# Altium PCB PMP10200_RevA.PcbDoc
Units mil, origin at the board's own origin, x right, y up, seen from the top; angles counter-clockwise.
Board outline 5387.5 x 1750 mil, 2 copper layers (Top Layer, Bottom Layer), stack 62 mil thick; 58 components, 32 nets, 132 pads, 50 vias.
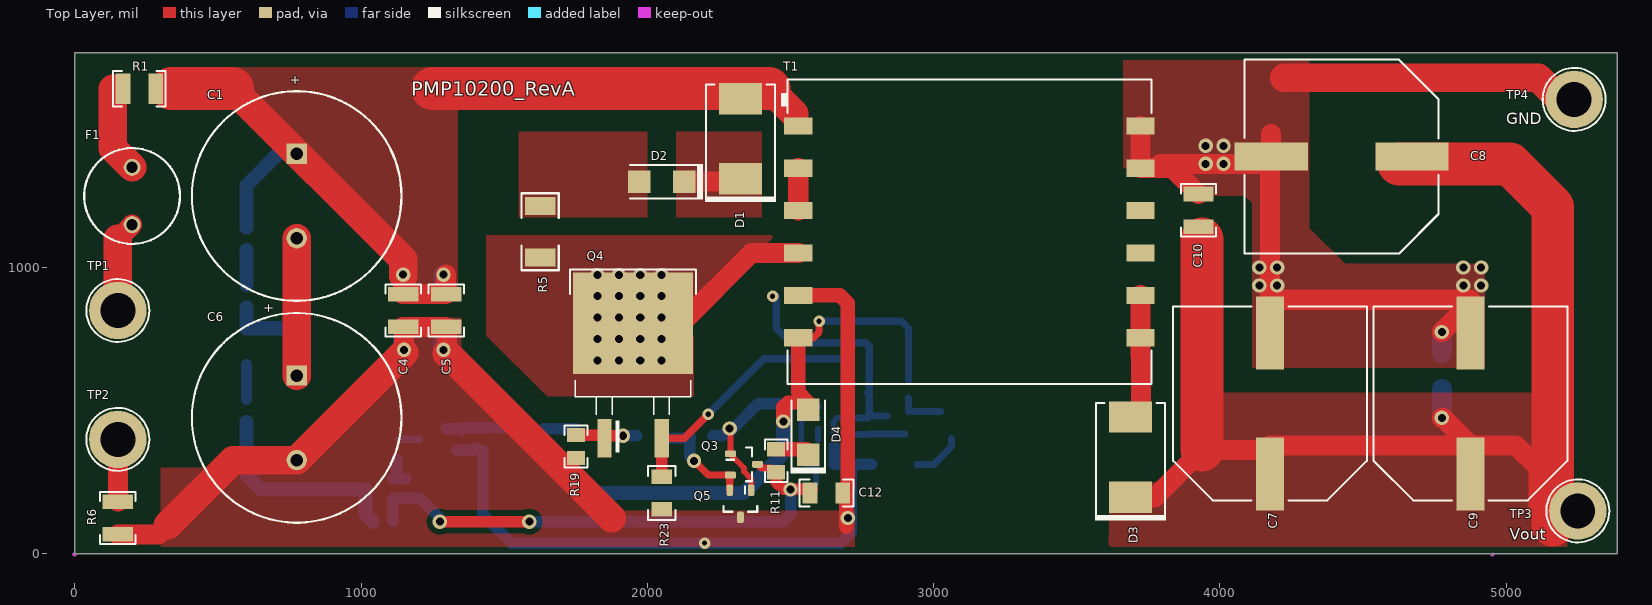
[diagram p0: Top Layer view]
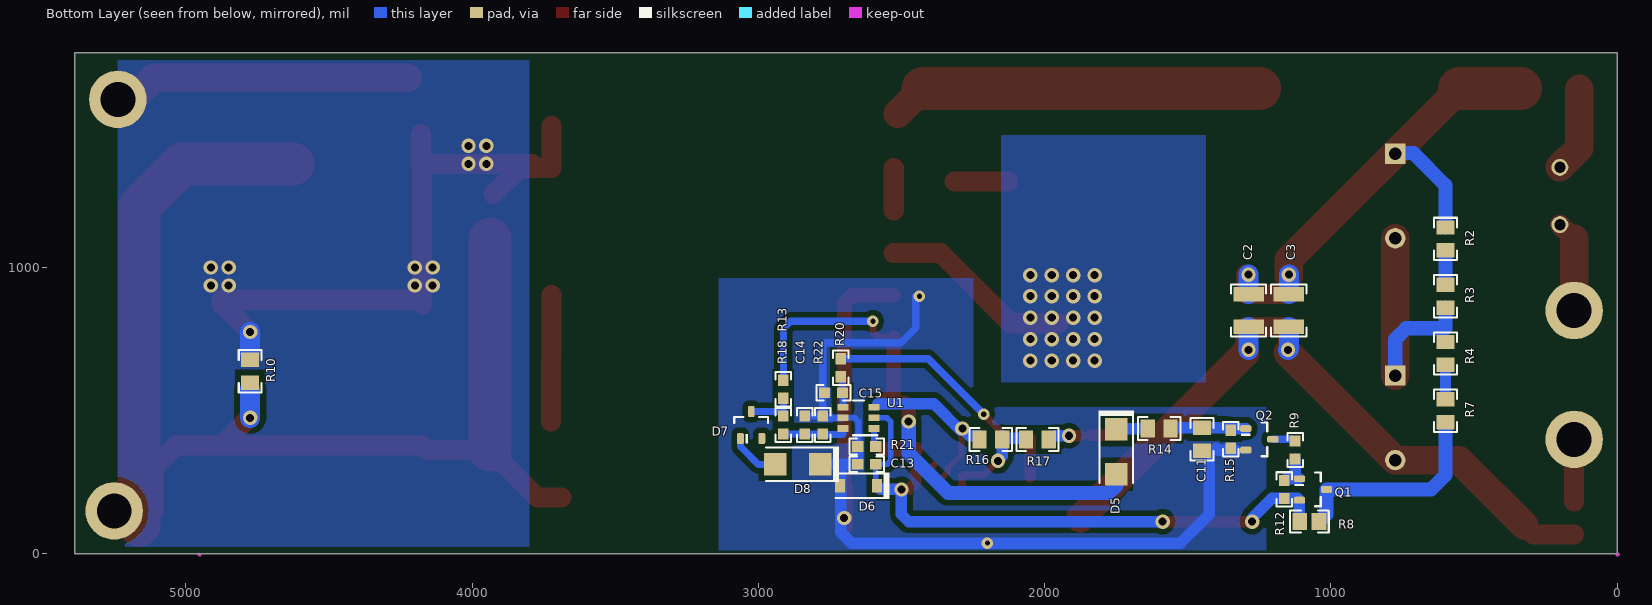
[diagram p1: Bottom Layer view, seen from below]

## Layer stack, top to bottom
Top Solder: solder mask 0.4, Solder Resist, Dk 3.5
Top Layer: signal copper 1.4
Dielectric1: core 59.2, FR-4, Dk 4.8
Bottom Layer: signal copper 1.4
Bottom Solder: solder mask 0.4, Solder Resist, Dk 3.5

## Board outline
0,0 5387.5,0 5387.5,1750 0,1750

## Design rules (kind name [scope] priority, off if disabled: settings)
AcuteAngle [All] p1: minimum=4.50000000000000E+0001 checktracksonly=FALSE
AssemblyTestPointUsage [All] p1: valid=2
Clearance Clearance_Keepouts [((IsTrack Or IsArc) And Not InPoly) And IsFree and IsKeepOut vs ((IsTrack Or IsArc) And Not InPoly) And IsFree and IsKeepOut] p1: gap=0
Clearance Clearance_BoardEdge_MountingHoles [OnCopper and InComponentClass('Mounting Holes') vs IsKeepOut] p2: gap=20
Clearance Clearance_BoardEdge_Poly [OnCopper and InPoly vs IsKeepOut] p3: gap=20
Clearance Clearance_BoardEdge [OnCopper and Not InComponentClass('Logo') and not InComponentClass('FiducialMark') and not InRegion(1000,500,4000,800) and Not IsKeepout vs IsKeepOut] p4: gap=20
Clearance Clearance_Poly [InPolygon] p5: gap=20
Clearance [All] p6: gap=7.87
ComponentClearance ComponentClearance_MountingHoles_FiducialMarks [InComponentClass('Mounting Holes') vs InComponentClass('FiducialMark')] p1: gap=50 collisioncheckmode=3 verticalgap=10 showdistances=FALSE
ComponentClearance ComponentClearance_Shunt [InComponentClass('Header') vs InComponentClass('Shunt')] p2: gap=0 collisioncheckmode=3 verticalgap=0 showdistances=FALSE
ComponentClearance ComponentClearance_Logo [InComponentClass('Logo')] p3: gap=50 collisioncheckmode=3 verticalgap=10 showdistances=FALSE
ComponentClearance ComponentClearance_ScrewToNut [(HasFootprint('NY PMS 440 0025 PH')) vs (HasFootprint('Keystone_1902C'))] p4: gap=5 collisioncheckmode=3 verticalgap=10 showdistances=FALSE
ComponentClearance ComponentClearance_MountingHoles [InComponentClass('Mounting Holes')] p5: gap=20 collisioncheckmode=3 verticalgap=100000 showdistances=FALSE
ComponentClearance ComponentClearance_SmallPassives [HasFootprint('0201*') or HasFootprint('0402*') or HasFootprint('0508') or HasFootprint('0603*') or HasFootprint('0612') or HasFootprint('0805*') or HasFootprint('0815*') or HasFootprint('0830*') or HasFootprint('1206*') or HasFootprint('1210*') or HasFootprint('1808*') or HasFootprint('1812*') or HasFootprint('1825*') or HasFootprint('2010*') or HasFootprint('2220*') or HasFootprint('2225*') or HasFootprint('2512*') or HasFootprint('2728*') or HasFootprint('3518*') vs HasFootprint('0201*') or HasFootprint('0402*') or HasFootprint('0508') or HasFootprint('0603*') or HasFootprint('0612') or HasFootprint('0805*') or HasFootprint('0815*') or HasFootprint('0830*') or HasFootprint('1206*') or HasFootprint('1210*') or HasFootprint('1808*') or HasFootprint('1812*') or HasFootprint('1825*') or HasFootprint('2010*') or HasFootprint('2220*') or HasFootprint('2225*') or HasFootprint('2512*') or HasFootprint('2728*') or HasFootprint('3518*')] p6: gap=20 collisioncheckmode=3 verticalgap=10 showdistances=FALSE
ComponentClearance ComponentClearance_THtoSMT [IsThruComponent vs IsSMTComponent] p7: gap=20 collisioncheckmode=3 verticalgap=30 showdistances=FALSE
ComponentClearance ComponentClearance_THtoTH [IsThruComponent vs IsThruComponent] p8: gap=20 collisioncheckmode=3 verticalgap=30 showdistances=FALSE
ComponentClearance [All] p9: gap=20 collisioncheckmode=3 verticalgap=10 showdistances=FALSE
DiffPairsRouting [All] p1: maxlimit=100 minlimit=10 mostfreqgap=10 toplayer_minwidth=15 toplayer_maxwidth=15 toplayer_prefwidth=15 bottomlayer_minwidth=15 bottomlayer_maxwidth=15 bottomlayer_prefwidth=15 maxuncoupledlength=1000
FabricationTestPointUsage TestPointUsage [All] p1: valid=2 allowmultiple=FALSE
FabricationTestpoint Testpoint [All] p1: side=3 testpointundercomponent=TRUE minsize=40 maxsize=100 preferedsize=60 minholesize=0 maxholesize=40 preferedholesize=32 testpointgrid=1 allowsidetop=TRUE allowsidebottom=TRUE usegrid=TRUE gridtolerance=0.01
FanoutControl Fanout_LCC [IsLCC] p1: bgadir=Out bgaviamode=Centered fanoutstyle=Auto fanoutdirection=Alternating viagrid=1 // Fanout_LCC (Default Rule)
FanoutControl Fanout_BGA [IsBGA] p2: bgadir=Out bgaviamode=Centered fanoutstyle=Auto fanoutdirection=Alternating viagrid=1 // Fanout_BGA (Default Rule)
FanoutControl Fanout_Default [All] p4: bgadir=Out bgaviamode=Centered fanoutstyle=Auto fanoutdirection=Alternating viagrid=1 // Fanout_Default (Default Rule)
FanoutControl Fanout_Small [(CompPinCount < 5)] p5: bgadir=Out bgaviamode=Centered fanoutstyle=Auto fanoutdirection=OutThenIn viagrid=1 // Fanout_Small (Default Rule)
HoleSize [All] p1: absolutevalues=TRUE maxlimit=251 minlimit=8 maxpercent=80.000 minpercent=20.000
MinimumAnnularRing MinimumAnnularRing_ThermalPadVias [IsVia and InAnyComponent] p1: minimumring=5.91
MinimumAnnularRing [All] p2: minimumring=9
MinimumSolderMaskSliver MinimumSolderMaskSliver_Logo [InComponentClass('Logo') vs InComponentClass('Logo')] p1: minsoldermaskwidth=0.7
MinimumSolderMaskSliver [All] p2: minsoldermaskwidth=3.94
PlaneConnect [All] p1: planeconnectstyle=Relief reliefexpansion=10 reliefentries=4 reliefconductorwidth=10 reliefairgap=10
PolygonConnect [All] p1: connectstyle=Direct reliefconductorwidth=10 reliefentries=4 polygonreliefangle="90 Angle" airgapwidth=10
RoutingVias ThermalPadVias [IsVia and InAnyComponent] p1: holewidth=7.87 width=19.68 viastyle="Through Hole" minholewidth=7.87 minwidth=19.68 maxholewidth=12.99 maxwidth=23.62
RoutingVias [All] p2: holewidth=16 width=34 viastyle="Through Hole" minholewidth=7.87 minwidth=26 maxholewidth=40 maxwidth=65
SilkToBoardRegionClearance [Not ((IsComment or IsDesignator) And (Hide <> 'False')) and not InRegion(1000,500,4000,800)] p1:
SilkToSilkClearance SilkToSilkClearance_Pb-FreeLogo [(HasFootprint('Pb-Free_Overlay_Medium') OR HasFootprint('Pb-Free_Overlay_Small')) vs (HasFootprint('Pb-Free_Overlay_Medium') OR HasFootprint('Pb-Free_Overlay_Small'))] p1 off: silktosilkclearance=0
SilkToSilkClearance [All] p2 off: silktosilkclearance=4
SilkToSolderMaskClearance "Silk to Solder Mask Opening" [All] p1 off: minsilkscreentomaskgap=4 clearancetoexposedcopper=FALSE
SolderMaskExpansion [All] p1: expansion=1.97
UnpouredPolygon [All] p1: allowunpoured=FALSE
Width [All] p1: maxlimit=160 minlimit=6 preferedwidth=10 minimp=50.000000 maximp=50.000000 favimp=50.000000 checkconnectedcopper=TRUE
14 further rules are at their usual default settings.

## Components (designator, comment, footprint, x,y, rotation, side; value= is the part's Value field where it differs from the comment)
C1 "TBD" EE_1800x2500 775,1250 r270 top
C2 "GRM32DR72J473KW01L" 1210 1287.5,850 r270 bottom
C3 "GRM32DR72J473KW01L" 1210 1146.85,850 r270 bottom
C4 "GRM32DR72J473KW01L" 1210 1146.85,850 r270 top
C5 "GRM32DR72J473KW01L" 1210 1296.85,850 r270 top
C6 "TBD" EE_1800x2500 775,475 r270 top
C7 "EEV-FK1H102M" SM_RADIAL_J16 4175,525 r90 top
C8 "EEV-FK1H102M" SM_RADIAL_J16 4425,1387.5 r180 top
C9 "EEV-FK1H102M" SM_RADIAL_J16 4875,525 r90 top
C10 "GRM32ER71H106KA12L" 1210 3925,1200 r90 top
C11 "GRM21BR71H104KA01L" 0805_HV 1450,400 r270 bottom
C12 "GRM31CR71H225KA88L" 1206 2625,212.5 r0 top
C13 "C1608X7R1H104K" 0603 2621,312.5 r0 bottom
C14 "DNP" 0603 2837.5,450 r90 bottom
C15 "DNP" 0603 2737.5,562.5 r0 bottom
D1 "SMCJ75A" SMC 2325,1450 r90 top
D2 "US1J-13-F" SMA 2050,1300 r180 top
D3 "MURS340T3G" SMC 3687.5,337.5 r90 top
D4 "US1G-13-F" SMA 2562.5,425 r90 top
D5 "US1G-13-F" SMA 1750,356.69 r270 bottom
D6 "MMSZ5257B-7-F" SOD-123 2650,237.5 r0 bottom
D7 "BAS21-7-F" SOT-23 3025,450 r90 bottom
D8 "SMAZ15" SMA 2862.5,312.5 r0 bottom
F1 "37214000001" FUSE_372 200,1250 r270 top
Q1 "BSS126" SOT-23 1062.5,225 r180 bottom
Q2 "2N7002-7-F" SOT-23 1250,400 r180 bottom
Q3 "MMBT3904" SOT-23 2337.5,312.5 r0 top
Q4 "STB13N80K5" DDPAK 1950,650 r90 top
Q5 "MMBT2907A" SOT-23 2325,175 r270 top
R1 "Used in BOM report" 1210 225,1625 r0 top
R2 "CRCW080530K1FKEA" 0805_HV 599.5,1100 r90 bottom
R3 "CRCW080530K1FKEA" 0805_HV 599.5,900 r90 bottom
R4 "CRCW080530K1FKEA" 0805_HV 599.5,700 r90 bottom
R5 "CRCW201020R0JNEF" 2010 1625,1125 r90 top
R6 "Used in BOM report" 1210 150,125 r270 top
R7 "CRCW080530K1FKEA" 0805_HV 599.5,500 r90 bottom
R8 "DNP" 0805 1075,112.5 r180 bottom
R9 "CRCW0603200KJNEA" 0603 1125,362.5 r270 bottom
R10 "CRCW080510K0FKEA" 0805_HV 4775,637.5 r270 bottom
R11 "RC0805FR-0710RL" 0805_HV 2450,325 r90 top
R12 "CRCW0603200KJNEA" 0603 1162.5,225 r270 bottom
R13 "CRCW060327K4FKEA" 0603 2912.5,575 r270 bottom
R14 "CRCW08050000Z0EA" 0805_HV 1600,437.5 r180 bottom
R15 "CRCW0603499KFKEA" 0603 1350,400 r90 bottom
R16 "CRCW08050000Z0EA" 0805_HV 2187.5,400 r180 bottom
R17 "CRCW08050000Z0EA" 0805_HV 2025,400 r180 bottom
R18 "CRCW060327K4FKEA" 0603 2912.5,450 r90 bottom
R19 "CRCW080510K0FKEA" 0805_HV 1750,375 r90 top
R20 "CRCW0603340RFKEA" 0603 2712.5,650 r90 bottom
R21 "Used in BOM report" 0603 2621,375 r180 bottom
R22 "CRCW060311K0FKEA" 0603 2775,450 r270 bottom
R23 "CSR1206FKR250" 1206 2050,212.5 r90 top
T1 "750315623" Wurth_750315623 3125,1125 r0 top
TP1 "Suggest using a net name here" Keystone1503-2 150,850 r0 top
TP2 "Suggest using a net name here" Keystone1503-2 150,400 r0 top
TP3 "Suggest using a net name here" Keystone1503-2 5250,150 r0 top
TP4 "Suggest using a net name here" Keystone1503-2 5237.5,1587.5 r0 top
U1 "UCC28700-Q1" DBV0006A_N 2650,475 r0 bottom

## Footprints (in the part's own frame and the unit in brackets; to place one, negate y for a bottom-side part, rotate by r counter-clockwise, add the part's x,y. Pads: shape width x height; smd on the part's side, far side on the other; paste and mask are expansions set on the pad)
0603 [mm] "0603 from SM-752 data"
  rect 1x0.95 smd: 1(-0.8,0) 2(0.8,0)
  silkscreen extent -1.52,-0.69 1.52,0.69, body extent -0.87,-0.47 0.87,0.47, height 0.85
0805 [mm] "0805 from SM-752 data"
  rect 1.3x1.5 smd: 1(-0.85,0) 2(0.85,0)
  silkscreen extent -1.72,-0.97 1.72,0.97, body extent -1.1,-0.72 1.1,0.72, height 1.1
0805_HV [mil] "0805 with 30mil clearance between pads"
  rect 50x63 smd: 1(-40,0) 2(40,0)
  silkscreen extent -74,-40 74,40, body extent -43,-29 43,29, height 57
1206 [mm] "1206 from SM-752 data"
  rect 1.3x1.85 smd: 1(-1.45,0) 2(1.45,0)
  silkscreen extent -2.4,-1.21 2.4,1.21, body extent -1.7,-0.9 1.7,0.9, height 1.35
1210 [mm] "1210 from SM-752 data"
  rect 1.3x2.7 smd: 1(-1.45,0) 2(1.45,0)
  silkscreen extent -2.32,-1.57 2.32,1.57, body extent -1.7,-1.35 1.7,1.35, height 1.35
2010 [mm] "Chip Capacitor, Body 5.08x2.54mm, IPC Medium Density"
  rect 1.6x2.7 smd: 1(-2.3,0) 2(2.3,0)
  silkscreen extent -3.42,-1.65 3.42,1.65, body extent -2.73,-1.45 2.73,1.45, height 1.66
DBV0006A_N [mm] "SOT23, 6-Leads, Body 2.9x1.6mm, Pitch 0.95mm, Lead Span 2.8mm, IPC Medium Density"
  rrect17% 1x0.6 smd: 1(-1.375,0.95) 2(-1.375,0) 3(-1.375,-0.95) 4(1.375,-0.95) 5(1.375,0) 6(1.375,0.95)
  silkscreen extent -1.68,-1.55 0.5,1.55, body extent -1.42,-1.46 1.42,1.46, height 1.12
DDPAK [mil] "D2-PAK, 3-Pads, Body 9.7x10.4mm (max), TO-263AB, using Vishay Silionix recommended pad sizes"
  rrect8% 135x49.49 smd: 1(-246.06,100) 3(-246.06,-100)
  rrect1% 355x420 smd paste-181.1: 4(155.51,0)
  silkscreen extent -295,-220 344,220, body extent -295,-202 324,202, height 180
EE_1800x2500 [mm] "PANASONIC"
  rect 1.8x1.8 hole 1.1: 1(-3.75,0)
  round 1.8 hole 1.1: 2(3.75,0)
  silkscreen extent -9.3,-9.3 9.3,9.3, body extent -9.18,-9.23 9.22,9.24, height 27.01
FUSE_372 [mm] "LITTELFUSE"
  round 1.5 hole 1: 1(-2.54,0) 2(2.54,0)
  silkscreen extent -4.25,-4.25 4.25,4.25, body extent -4.26,-4.26 4.26,4.26, height 8
Keystone1503-2 [mm] "Double Turret"
  round 5.1 hole 3.1: 1(0,0)
  silkscreen extent -2.79,-2.79 2.79,2.79, body extent -2.4,-2.4 2.38,2.4, height 9.22
SM_RADIAL_J16 [mm] "16 x 16.5mm:  Panasonic J16"
  rect 6.5x2.5 smd: 1(-6.25,0) 2(6.25,0)
  silkscreen extent -8.6,-8.6 8.6,8.6, body extent -8.6,-8.6 8.6,8.6, height 17
SMA [mm] "Molded Diode, 2-Leads, Body 4.3x2.6mm, IPC Medium Density, based on OnSemi component dimensions and land pattern"
  rect 2x2 smd: 1(-2,0) 2(2,0)
  silkscreen extent -3.66,-1.57 2.79,1.57, body extent -2.6,-1.3 2.6,1.3, height 2.42
SMC [mil] "Molded Diode, 2-Leads, Body 6.9x5.8mm, IPC Medium Density, based on OnSemi component dimensions and land patterns"
  rect 110x150 smd: 1(-140.49,0) 2(140.49,0)
  silkscreen extent -221,-124 189,123, body extent -156,-116 156,116, height 91
SOD-123 [mm] "On Semi recommended land pattern"
  rect 0.915x1.22 smd: 1(-1.637,0) 2(1.637,0)
  silkscreen extent -2.74,-1.17 2.03,1.17, body extent -1.93,-0.9 1.93,0.9, height 1.35
SOT-23 [mm] "SOT23, 3-Leads, Body 2.9x1.3mm, Pitch 0.95mm, Lead Span 2.5mm, IPC Medium Density"
  rrect50% 1x0.6 smd: 1(-1.2,0.95) 2(-1.2,-0.95) 3(1.2,0)
  silkscreen extent -1.62,-1.5 0.7,1.5, body extent -1.16,-1.45 1.21,1.45, height 1
Wurth_750315623 [mm] "SMD, 12-Leads, Body 32.31x27.03mm, Pitch 3.76mm"
  rect 2.5x1.52 smd: 1(-15.19,9.4) 2(-15.19,5.64) 3(-15.19,1.88) 4(-15.19,-1.88) 5(-15.19,-5.64) 6(-15.19,-9.4) 7(15.19,-9.4) 8(15.19,-5.64) 9(15.19,-1.88) 10(15.19,1.88) 11(15.19,5.64) 12(15.19,9.4)
  silkscreen extent -16.7,-13.51 16.15,13.51, body extent -16.15,-13.51 16.15,13.51, height 13.98

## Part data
C1 C6: library part EEU-EE2G680, "CAP, AL"
C2 C3 C4 C5: "CAP, CERM, 0.047 µF, 630 V, +/- 10%, X7R, 1210"
C7 C8 C9: "CAP, AL, 1000 µF, 50 V, +/- 20%, 0.073 ohm, SMD"
C10: "CAP, CERM, 10 µF, 50 V, +/- 10%, X7R, 1210"
C11: "CAP, CERM, 0.1 µF, 50 V, +/- 10%, X7R, 0805"
C12: "CAP, CERM, 2.2 µF, 50 V, +/- 10%, X7R, 1206"
C13: "CAP, CERM, 0.1 µF, 50 V, +/- 10%, X7R, 0603"
C14 C15: library part Capacitor, "CAP, CERM, xxxF, xxV, [TempCo], xx%, [PackageReference]"
D1: "Diode, TVS, Uni, 75 V, 1500 W, SMC"
D2: "Diode, Ultrafast, 600 V, 1 A, SMA"
D3: "Diode, Ultrafast, 400 V, 3 A, SMC"
D4 D5: "Diode, Ultrafast, 400 V, 1 A, SMA"
D6: "Diode, Zener, 33 V, 500 mW, SOD-123"
D7: "Diode, Switching, 200 V, 0.2 A, SOT-23"
D8: library part BZG03C15G, "Diode, Zener, 15 V, SMA"
F1: "Fuse, 4 A, 250 V, TH"
Q1: library part "BSS126 H6906", "MOSFET, N-CH, 600 V, 0.021 A, SOT-23"
Q2: "MOSFET, N-CH, 60 V, 0.17 A, SOT-23"
Q3: library part "MMBT3904, Fairchild Semiconductor", "Transistor, NPN, 40 V, 0.2 A, SOT-23"
Q4: library part STB11N65M5, "MOSFET, N-CH, 800 V, DDPAK"
Q5: library part "MMBT2907A, Fairchild Semiconductor", "Transistor, PNP, 60 V, 0.8 A, SOT-23"
R1 R6 R8 R21: library part Resistor, "RES, xxx ohm, x%, xW, [PackageReference]"
R2 R3 R4 R7: "RES, 30.1 k, 1%, 0.125 W, 0805"
R5: "RES, 20, 5%, 0.75 W, 2010"
R9 R12: "RES, 200 k, 5%, 0.1 W, 0603"
R10 R19: "RES, 10.0 k, 1%, 0.125 W, 0805"
R11: "RES, 10.0, 1%, 0.125 W, 0805"
R13 R18: "RES, 27.4 k, 1%, 0.1 W, 0603"
R14 R16 R17: "RES, 0, 5%, 0.125 W, 0805"
R15: "RES, 499 k, 1%, 0.1 W, 0603"
R20: "RES, 340, 1%, 0.1 W, 0603"
R22: "RES, 11.0 k, 1%, 0.1 W, 0603"
R23: "RES, 0.25, 1%, 0.5 W, 1206"
T1: "Transformer, 100 uH, SMT"
TP1 TP2 TP3 TP4: library part 1503-2, "Terminal, Turret, TH, Double"
U1: library part UCC28700DBVR, "Constant-Voltage, Constant-Current Controller With Primary-Side Regulation, DBV0006A"

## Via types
v1: diameter 50, hole 28, Top Layer to Bottom Layer, 46 vias
v2: diameter 40, hole 18, Top Layer to Bottom Layer, 4 vias

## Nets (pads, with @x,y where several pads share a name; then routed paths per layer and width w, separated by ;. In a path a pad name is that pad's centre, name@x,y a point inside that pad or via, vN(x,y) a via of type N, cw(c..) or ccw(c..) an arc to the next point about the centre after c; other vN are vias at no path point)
GND: C7.2 C8.2 C9.2 C10.2 R10.1 T1.11 T1.12 TP4.1 | length 3313
  Top Layer w70: T1.12 T1.11 3835.04,1347.05 C10.2 ; 3790.45,1362.5 4178.94,1362.5 4178.94,1466.44 ; C7.2@4175,871.06 C7.2@4175,887.5 ; C8.2@4175,1358.56 C7.2@4175,887.5 ; v1(4775,775) 4871.06,871.06 C9.2@4875,871.06 ; C9.2@4875,887.5 C7.2@4175,887.5
  Top Layer w100: 4225,1662.5 5100,1662.5 ; 5112.5,1662.5 5187.5,1587.5 TP4.1
  Bottom Layer w70: R10.1@4775,700 v1(4775,775)
  other v1: 4137.5,937.5 4200,937.5 4850,937.5 4912.5,937.5 4137.5,1000 4200,1000 4850,1000 4912.5,1000 3950,1362.5 4012.5,1362.5 3950,1425 4012.5,1425
NetC1_1: C1.1 C2.1 C3.1 C4.1 C5.1 D1.2 R1.2 R2.2 T1.1 | length 3197.1
  Top Layer w70: v1@1146.85,971.85 C4.1 C5.1 v1@1296.85,975
  Top Layer w100: 550,1625 1146.85,1028.15 v1(1146.85,975) v1@1146.85,971.85 ; 2425,1625 2512.5,1537.5
  Top Layer w150: 337.5,1625 550,1625 ; 1250,1625 2425,1625
  Bottom Layer w50: R2.2 599.5,1287 712.5,1400 C1.1@772.64,1400
  Bottom Layer w70: C3.1 v1(1146.85,975) ; C2.1 v1(1287.5,975)
NetC1_2: C1.2 C6.1 R3.1 R4.2 | length 870.6
  Top Layer w100: C6.1 C1.2
  Bottom Layer w50: R3.1 599.5,787.5 737.5,787.5 775,750 C6.1
NetC7_1: C7.1 C8.1 C9.1 C10.1 D3.1 R10.2 TP3.1 | length 4366.9
  Top Layer w70: D3.1 3772.01,197.01 3937.5,362.5 C7.1@4158.56,362.5 ; C7.1@4175,378.94 C9.1@4875,378.94 ; C8.1@4671.06,1362.5 C8.1@4683.56,1350 ; v1(4775,475) 4778.94,475 C9.1@4875,378.94 ; 5112.5,150 5112.5,300 5033.56,378.94 C9.1@4875,378.94
  Top Layer w150: 3937.5,362.5 3937.5,1100 ; C8.1@4625,1362.5 5012.5,1362.5 5162.5,1212.5 5162.5,100
  Bottom Layer w70: v1(4775,475) R10.2@4775,575
NetC11_1: C11.1 Q2.1 R14.2 R15.2 | length 229.2
  Bottom Layer w40: Q2.1 1344.09,437.4 R15.2 ; R15.2@1358.5,440 C11.1 ; C11.1@1475,440 R14.2@1557.5,440
NetC12_1: C12.1 C13.1 D6.1 Q1.2 Q3.3 R8.1 R11.1 R12.2 U1.2 | length 2246.6
  Top Layer w25: Q3.3 2397.24,300 2435,300 R11.1
  Top Layer w40: v1(1275,112.5) v1(1587.5,112.5) ; R11.1 2450,250 2475,225 v1(2500,225) C12.1@2575.41,225
  Bottom Layer w20: D6.1@2589.5,241.47 C13.1 2550,312.5 2537.5,325 2537.5,462.5 2550,475 U1.2
  Bottom Layer w40: R8.1@1109.74,113.78 Q1.2 ; Q1.2@1115.65,193.5 R12.2 1206.5,193.5 1275,125 v1(1275,112.5) ; v1(1587.5,112.5) 2475,112.5 2500,137.5 v1(2500,225) D6.1@2573.03,225
NetC14_1: C14.1 R18.1 R22.2 U1.6 | length 217.1
  Bottom Layer w25: U1.6 2704.13,416.63 2773.13,416.63 R22.2 C14.1 R18.1@2899.51,418.5
NetC15_1: C15.1 R20.1 U1.4 | length 97.7
  Bottom Layer w25: U1.4 C15.1@2704.13,560.63 ; C15.1 R20.1@2706,612.01
NetD1_1: D1.1 D2.1 | length 186.8
  Top Layer w70: D2.1 D1.1@2315.49,1300
NetD2_2: D2.2 R5.2
NetD3_2: D3.2 T1.7 T1.8 | length 442.4
  Top Layer w70: T1.8@3723.03,904.92 D3.2@3725,462.5
NetD4_1: D4.1 R11.2 | length 106.2
  Top Layer w50: R11.2 D4.1@2556.24,365
NetD4_2: D4.2 D5.2 R13.1 T1.6 | length 1970.4
  Top Layer w25: T1.6 2579.92,754.92 2600,775 v2(2600,812.5)
  Top Layer w50: v1(2475,462.5) 2475,512.5 2491.24,528.74 2562.5,528.74 2526.97,564.27 T1.6
  Bottom Layer w25: v2(2600,812.5) 2887.5,812.5 2912.5,787.5 R13.1
  Bottom Layer w50: D5.2@1762.5,265.45 D5.2 1750,237.5 1775,212.5 2336.91,212.5 2475,350.59 v1(2475,462.5)
NetD5_1: D5.1 R14.1 | length 107.9
  Bottom Layer w40: R14.1 D5.1@1747.93,437.5
NetD7_1: D7.1 D8.2 | length 174.8
  Bottom Layer w25: D8.2 3000,312.5 3062.5,375 D7.1@3062.5,402.66
NetD7_3: D7.3 R13.2 R18.2 | length 143
  Bottom Layer w25: R18.2@2912.5,497.24 R13.2 ; R18.2@2928.25,497.24 D7.3
NetF1_1: F1.1 R1.1 | length 303.5
  Top Layer w70: 132.48,1623.68 133.8,1625
  Top Layer w100: 132.48,1623.68 132.48,1417.52 F1.1
NetF1_2: F1.2 TP1.1 | length 320.7
  Top Layer w70: 150,1100 F1.2
  Top Layer w100: TP1.1 150,1100
NetQ1_1: Q1.1 R9.2 R12.1 | length 100.2
  Bottom Layer w40: Q1.1 R12.1@1156.59,262.4 ; 1125,277.66 R9.2
NetQ1_3: Q1.3 R7.1 R8.2 | length 744.6
  Bottom Layer w50: R7.1 599.5,275.5 650,225 Q1.3 1015.26,138.78 R8.2
NetQ2_3: Q2.3 R9.1 | length 71.8
  Bottom Layer w25: R9.1@1131,400 Q2.3
NetQ3_1: Q3.1 Q5.1 R16.1 U1.3 | length 662.8
  Top Layer w20: v1(2287.5,437.5) 2290.26,434.74 Q3.1 2290.26,347.24 2337.5,300 2337.5,287.5 2362.4,262.6 Q5.1
  Bottom Layer w25: 2583.27,525 U1.3
  Bottom Layer w40: R16.1@2227.5,412.5 2262.5,412.5 v1(2287.5,437.5) ; v1@2293.75,431.25 2387.5,525 2583.27,525
NetQ3_2: Q3.2 Q5.2 R16.2 R17.1 | length 354.8
  Top Layer w25: v1(2162.5,325) 2212.4,275.1 Q3.2 ; Q5.2 Q3.2@2287.6,272.44
  Bottom Layer w40: R17.1@2087.5,403.94 R16.2@2150,403.94 ; R16.2@2147.5,412.5 2147.5,340 v1(2162.5,325)
NetQ4_1: Q4.1 R17.2 R19.2 | length 177.9
  Top Layer w40: R19.2 Q4.1@1838.94,415 ; 1875,412.5 v1@1916.44,412.5
  Bottom Layer w40: v1(1915,412.5) R17.2@1962.5,412.5
NetQ4_3: Q4.3 R20.2 R23.2 | length 911.8
  Top Layer w25: Q4.3 2128.94,403.94 v2(2212.5,487.5)
  Top Layer w40: R23.2 Q4.3
  Bottom Layer w25: v2(2212.5,487.5) 2406.5,681.5 R20.2
NetQ4_4: Q4.4 R5.1 T1.4 | length 678.6
  Top Layer w70: Q4.4 2118.01,805.51 2363.48,1050.98 T1.4
  other v1: 1825,675 1900,675 1975,675 2050,675 1825,750 1900,750 1975,750 2050,750 1825,825 1900,825 1975,825 2050,825 1825,900 1900,900 1975,900 2050,900 1825,973.43 1900,973.43 1975,973.43 2050,973.43
NetR2_1: R2.1 R3.2 | length 120
  Bottom Layer w50: R3.2 R2.1
NetR4_1: R4.1 R7.2 | length 120
  Bottom Layer w40: R7.2 R4.1
NetR6_1: R6.1 TP2.1 | length 217.9
  Top Layer w70: R6.1 TP2.1
NetR21_2: R21.2 U1.1 | length 40
  Bottom Layer w20: 2595.87,397.64 U1.1
NetT1_2: T1.2 T1.3 | length 148
  Top Layer w70: T1.3 T1.2
PGND: C2.2 C3.2 C4.2 C5.2 C6.2 C11.2 C12.2 C13.2 C14.2 C15.2 D6.2 D8.1 Q2.2 Q5.3 R6.2 R15.1 R19.1 R21.1 R22.1 R23.1 T1.5 U1.5 | length 6550.8
  Top Layer w50: T1.5 2672.05,902.95 2700,875 C12.2@2700,235.41 ; 2694.59,94.59 C12.2@2694.59,230
  Top Layer w70: R6.2 292.91,67.91 325,100 ; C4.2 C5.2 C5.2@1296.85,789.76 ; v1@1150,702.36 v1(1150,712.5) C4.2@1150,789.76 ; v1@1300,712.5 C5.2@1300,789.76
  Top Layer w100: 325,100 552.36,327.36 C6.2 v1@1150,702.36 ; v1@1300,700 1875,125
  Bottom Layer w20: R21.1@2650,387.5 2650,462.5 2662.5,475 U1.5
  Bottom Layer w25: v2@2450,900 2450,788.98 2501.48,737.5 2762.5,737.5 2775,725 2775,568.5 C15.2 2775,556.5 R22.1 ; U1.5 2768.5,475 R22.1 ; C14.2 R22.1
  Bottom Layer w40: R15.1@1334.74,362.6 1394.09,362.6 1400,368.5 ; C11.2@1425,360 1425,137.5 1525,37.5 2300,37.5 2675,37.5 2712.5,75 2712.5,312.5 ; C13.2 2712.5,312.5 ; C13.2@2652.5,324.47 R21.1 ; D8.1 2712.5,312.5
  Bottom Layer w70: C3.2 1146.85,715.65 v1(1150,712.5) ; v1(1287.5,712.5) C2.2
  other v1: 2700,125
  other v2: 2200,37.5 2437.5,900
pads on no net: D7.2 T1.9 T1.10

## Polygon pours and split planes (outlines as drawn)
NetD2_2 on Top Layer "Top Layer-No Net 1" (solid, remove dead copper, pour order 4): 2000,1175 1550,1175 1550,1475 2000,1475
NetQ4_4 on Top Layer "Top Layer-No Net" (solid, remove dead copper, pour order 8): 2162.5,550 1650,550 1437.5,762.5 1437.5,1112.5 2162.5,1112.5
NetD1_1 on Top Layer "Top Layer-No Net 2" (solid, remove dead copper, pour order 10): 2100,1475 2400,1475 2400,1175 2100,1175
PGND on Top Layer "Top Layer-No Net 3" (solid, remove dead copper, pour order 12): 1350,825 1350,675 1375,675 1800,250 1900,150 2725,150 2725,25 300,25 300,300 775,300 1200,825
NetQ4_4 on Top Layer "Top Layer-No Net 4" (solid, remove dead copper, pour order 17): 2446.65,1112.5 2025.33,1112.5 2062.83,1075 2062.83,713.33
NetC1_1 on Top Layer "Top Layer-No Net 5" (solid, remove dead copper, pour order 19): 438.41,1700 1337.5,1700 1337.5,912.5 1128.15,912.5 1125,915.65 1125,987.5
NetC7_1 on Top Layer "Top Layer-No Net 6" (solid, remove dead copper, pour order 21): 3616.45,250 3775,250 3931.25,381.25 3950,562.5 4087.5,562.5 5212.5,562.5 5212.5,25 3611.71,25
GND on Top Layer "Top Layer-No Net 7" (solid, remove dead copper, pour order 23): 4925,650 4112.5,650 4112.5,1225 4087.5,1250 4075,1250 3891.93,1250 3875,1266.93 3794.88,1347.05 3775,1347.05 3665.45,1347.05 3662.5,1350 3662.5,1725 4312.5,1725 4325,1737.5 4312.5,1725 4312.5,1150 4312.5,1137.5 4437.5,1012.5 4925,1012.5
GND on Bottom Layer "Bottom Layer-No Net 2" (solid, remove dead copper, pour order 13): 3800,1725 3800,25 5237.5,25 5237.5,1725
PGND on Bottom Layer "Bottom Layer-No Net 1" (solid, remove dead copper, pour order 11): 1225,512.5 2250,512.5 2250,962.5 3137.5,962.5 3137.5,12.5 1225,12.5
NetQ4_4 on Bottom Layer "Bottom Layer-No Net" (solid, remove dead copper, pour order 15): 2151.77,600 1437.5,600 1437.5,1462.5 2151.77,1462.5

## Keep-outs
Keep-Out Layer:
  lines w10: -5,0 ccw(c0,0) 0,-5 cw(c0,0) -5,0 ; 70,1900 cw(c75,1900) 75,1905 ccw(c75,1900) 70,1900 ; 4950,-5 ccw(c4950,0) 4955,0 cw(c4950,0) 4950,-5 ; 5025,1905 cw(c5025,1900) 5030,1900 ccw(c5025,1900) 5025,1905
  text ".Layer_Name" at 577,-858.49 h60

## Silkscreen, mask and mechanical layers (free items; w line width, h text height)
Top Overlay:
  text "PMP10200_RevA" at 1175,1600 h50
  text "GND" at 5000,1500 h40
  text "Vout" at 5012.5,50 h40
  text ".Layer_Name" at 577,-858.49 h30
Bottom Overlay:
  text ".Layer_Name" at 577,-858.49 h30
Top Paste:
  text ".Layer_Name" at 577,-858.49 h60
Bottom Paste:
  text ".Layer_Name" at 577,-858.49 h60
Top Solder:
  text ".Layer_Name" at 577,-858.49 h60
  text ".Layer_Name" at 577,-858.49 h60
Bottom Solder:
  text ".Layer_Name" at 577,-858.49 h60
Drill Guide:
  text ".Layer_Name" at 577,-858.49 h60
M1 Board Outline:
  the board outline again, w10
M2 Board Dimensions:
  rectangle: 0,-275 125,-150
  rectangle: 125,-400 500,-275
  lines w7: 0,-275 1000,-275 ; 125,-400 125,-150 ; 250,-400 250,-150 ; 500,-400 500,-150 ; 750,-400 750,-150 ; 0,-400 0,-150 1000,-150 1000,-400 0,-400
  text ".Layer_Name" at 577,-858.49 h60
M3 3D STEP Top:
  text ".Layer_Name" at 577,-858.49 h60
M4 3D STEP Bottom:
  text ".Layer_Name" at 577,-858.49 h60
M5 Assembly Top:
  lines w10: -292,-930.17 6308,-930.17 ; -292,-726.83 6310,-726.83 ; -292,-523.5 -292,-1133.5 3713,-1133.5 ; 1284,-1133.5 -291.5,-1133.5 -291.5,-523.5 6310,-523.5
  text ".VersionControl_RevNumber" at 4982,-655.67 h60
M6 Assembly Bottom:
  lines w10: -292.5,-727.33 6309.5,-727.33 ; -290.5,-930.67 6309.5,-930.67 ; 2304.5,-1134 -292.5,-1134 -292.5,-524 6309,-524
  text ".VersionControl_RevNumber" at 1035.5,-656.17 h60
M9 Title Sheet:
  drawing of 57 lines, arcs and shapes, not listed
  text "1" at 739.84,8036.5 h70
  text "2" at 3235.5,8036.5 h70
  text "3" at 5724.84,8036.5 h70
  text "4" at 8231.51,8036.5 h70
  text "5" at 10730.5,8036.5 h70
  text "6" at 13235.5,8036.5 h70
  text "A" at -416.5,6893.5 h70
  text "A" at 14383.5,6893.5 h70
  text "B" at -416.5,4513.5 h70
  text "B" at 14383.5,4513.5 h70
  text "C" at -416.5,2138.5 h70
  text "C" at 14383.5,2138.5 h70
  text "PROJECT TITLE:" at 11343.5,277.5 h45
  text "PMP10200" at 11393.5,144.17 h70
  text "DESIGNED FOR:" at 11343.5,-23.5 h45
  text "D" at -416.5,-231.5 h70
  text "D" at 14383.5,-231.5 h70
  text "FILE NAME:" at 11343.5,-323.5 h45
  text "PMP10200_RevA" at 11393.5,-443.5 h70
  text "Texas Instruments (TI) and/or its licensors do not warrant the accuracy or completeness of this specification" at 6374,-605.34 h45
  text "ENGINEER:" at 11343.5,-613.5 h45
  text "LAYOUT BY:" at 12848.5,-613.5 h45
  text "or any information contained therein. TI and/or its licensors do not warrant that this design will meet" at 6329.01,-718 h45
  text "F. Mueller" at 11393.5,-768.49 h70
  text "F. Mueller" at 12899,-768.49 h70
  text "the specifications, will be suitable for your application or fit for any particular purpose, or will operate in" at 6329.01,-830.67 h45
  text ".Layer_Name" at 577,-858.49 h60
  text "ALTIUM DESIGNER VERSION:" at 12848.5,-923.5 h45
  text "an implementation. TI and/or its licensors do not warrant that the design is production worthy. You should" at 6329.01,-943.33 h45
  text "completely validate and test your design implementation to confirm the system functionality for your application." at 6374,-1056 h45
  text "1" at 739.84,-1263.5 h70
  text "2" at 3235.5,-1263.5 h70
  text "3" at 5724.84,-1263.5 h70
  text "4" at 8231.51,-1263.5 h70
  text "5" at 10730.5,-1263.5 h70
  text "6" at 13235.5,-1263.5 h70
M10 Fab Notes:
  text ".Layer_Name" at 577,-858.49 h60
M11 Gerber Information:
  lines w10: -292,-930.17 6308,-930.17 ; -292,-726.83 6310,-726.83 ; -292,-523.5 -292,-1133.5 3713,-1133.5 ; 1284,-1133.5 -291.5,-1133.5 -291.5,-523.5 6310,-523.5
M13 Component Bodies Top:
  text ".Layer_Name" at 577,-858.49 h60
M14 Component Bodies Bottom:
  text ".Layer_Name" at 577,-858.49 h60
M15 Courtyards Top:
  text ".Layer_Name" at 577,-858.49 h60
M16 Courtyards Bottom:
  text ".Layer_Name" at 577,-858.49 h60
Drill Drawing:
  text ".Layer_Name" at 577,-858.49 h60

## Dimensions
0,0 to 5387.5,0 on M2 Board Dimensions
0,0 to 0,1750 on M2 Board Dimensions
0,-400 to 1000,-400 on M2 Board Dimensions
